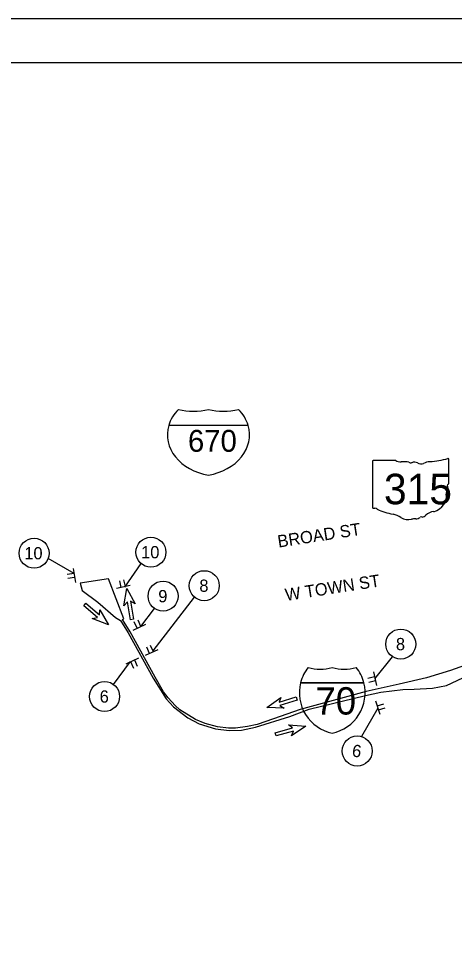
# Model space of a CAD drawing. Extents: x 0 to 680, y 0 to 440.
# Drawn here: x 318.1 to 417.5, y 225.4 to 440 of the extents above; entities that cross this region are included whole.
import ezdxf

# ---------------------------------------------------------------- set-up
doc = ezdxf.new("R2010")
doc.units = 0
for name, color, linetype in [('GM_X_Corporation_Text', 7, 'Continuous'), ('GM_X_County', 7, 'Continuous'), ('GM_X_Major_Lake', 7, 'Continuous'), ('GM_X_Major_River', 7, 'Continuous'), ('GM_X_Major_River_Text', 7, 'Continuous'), ('GM_X_Minor_Lake', 7, 'Continuous'), ('GM_X_Minor_River_Text', 7, 'Continuous'), ('GM_X_Unincorporated_Location', 7, 'Continuous'), ('GM_X_Unincorporated_Text', 7, 'Continuous')]:
    doc.layers.add(name, color=color, linetype=linetype)

msp = doc.modelspace()

# ---------------------------------------------------------------- linework, layer by layer
at = {"layer": 'GM_X_Corporation_Text'}
msp.add_lwpolyline([(419.85, 292.29), (416.65, 291.16), (411.19, 289.5), (404.98, 288.04), (397.46, 286.34), (382.37, 282.22), (376.24, 280.1), (372.51, 278.83), (370.32, 278.34), (367.58, 277.98), (365.97, 277.99), (363.45, 278.29), (360.65, 279.07), (358.44, 279.98), (354.91, 282.18), (353.81, 283.15), (352.17, 284.92), (351.18, 286.31), (349.21, 289.64), (343.56, 300.01), (341.8, 302.82), (342.05, 302.96), (338.55, 312.08), (332.09, 311.12), (332.58, 309.43), (336.11, 306.79), (340.18, 303.22), (341.35, 302.58), (343.11, 299.77), (348.76, 289.39), (351.72, 284.68), (353.39, 282.88), (356.68, 280.34), (359.3, 278.98), (363.03, 277.82), (366.12, 277.46), (368.92, 277.55), (372.16, 278.18), (379.97, 280.67), (384.44, 282.31), (397.27, 285.46), (400.81, 286.17), (405.8, 286.78), (408.42, 286.86), (412.57, 287.14), (415.79, 287.72), (420.78, 290.12)], dxfattribs=at)
at = {"layer": 'GM_X_County'}
msp.add_lwpolyline([(0, 0), (680, 0), (680, 440), (0, 440)], close=True, dxfattribs=at)
at = {"layer": 'GM_X_Major_Lake'}
for p, q in [((342.1, 305.93), (342.77, 309.84)), ((342.77, 309.84), (342.77, 309.84)), ((342.77, 309.84), (344.67, 306.36)), ((344.67, 306.36), (343.63, 306.95)), ((343.63, 306.95), (344.31, 302.88)), ((332.93, 305.95), (333.42, 306.52)), ((336.07, 303.26), (332.93, 305.95)), ((333.18, 306.23), (333.18, 306.23)), ((333.42, 306.52), (336.55, 303.83)), ((336.55, 303.83), (336.59, 305.03)), ((336.59, 305.03), (338.59, 301.6)), ((342.89, 306.82), (342.1, 305.93)), ((343.57, 302.75), (342.89, 306.82)), ((334.89, 303.05), (336.07, 303.26)), ((338.59, 301.6), (334.89, 303.05)), ((344.31, 302.88), (343.57, 302.75)), ((343.94, 302.82), (343.94, 302.82)), ((338.59, 301.6), (338.59, 301.6)), ((374.76, 282.66), (377.97, 285.01)), ((377.52, 283.9), (381.47, 285.11)), ((377.97, 285.01), (377.52, 283.9)), ((381.69, 284.39), (377.74, 283.18)), ((381.47, 285.11), (381.69, 284.39)), ((381.58, 284.75), (381.58, 284.75)), ((374.76, 282.66), (374.76, 282.66)), ((378.73, 282.51), (374.76, 282.66)), ((377.74, 283.18), (378.73, 282.51)), ((376.65, 276.93), (380.63, 278.02)), ((376.85, 276.21), (376.65, 276.93)), ((380.83, 277.3), (376.85, 276.21)), ((380.63, 278.02), (379.66, 278.72)), ((379.66, 278.72), (383.62, 278.46)), ((383.62, 278.46), (380.35, 276.21)), ((380.35, 276.21), (380.83, 277.3)), ((383.62, 278.46), (383.62, 278.46)), ((376.75, 276.57), (376.75, 276.57))]:
    msp.add_line(p, q, dxfattribs=at)
at = {"layer": 'GM_X_Major_River'}
for p, q in [((370.46, 347.12), (352.33, 347.12)), ((370.46, 347.12), (352.33, 347.12)), ((382.46, 288.35), (396.88, 288.35)), ((396.88, 288.35), (382.46, 288.35)), ((396.88, 288.35), (382.46, 288.35))]:
    msp.add_line(p, q, dxfattribs=at)
for centre, start, end in [((391.55, 286.05), 141.669, 165.8066), ((386.93, 300.83), 253.0091, 286.9909), ((392.41, 300.83), 253.0091, 286.9909), ((387.8, 286.05), 14.1934, 38.331), ((391.55, 286.05), 165.8066, 258.463), ((387.8, 286.05), 281.537, 14.1934)]:
    msp.add_arc(centre, 9.38, start, end, dxfattribs=at)
for centre, start_param, end_param in [((363.74, 344.98), 2.47259, 2.911027), ((357.98, 359.76), 4.415841, 5.008937), ((364.82, 359.76), 4.415841, 5.008937), ((359.06, 344.98), 0.230566, 0.669003), ((363.74, 344.98), 2.911027, 4.511031), ((359.06, 344.98), 4.913747, 6.513751)]:
    msp.add_ellipse(centre, major_axis=(11.72, 0), ratio=0.8, start_param=start_param, end_param=end_param, dxfattribs=at)
at = {"layer": 'GM_X_Minor_Lake'}
for p, q in [((330.71, 313.32), (324.8, 316.72)), ((342.31, 310.2), (346.05, 315.55)), ((348.78, 295.63), (358.24, 307.87)), ((346, 301.18), (349.08, 305.3)), ((399.44, 289.25), (403.45, 294.3)), ((339.76, 287.96), (343.61, 293.17)), ((400.11, 282.54), (396.33, 276.06))]:
    msp.add_line(p, q, dxfattribs=at)
for centre in [(321.59, 317.94), (348.27, 318.17), (360.44, 310.52), (351.04, 308.13), (405.32, 297.18), (337.69, 285.21), (395.37, 272.76)]:
    msp.add_circle(centre, 3.43, dxfattribs=at)
at = {"layer": 'GM_X_Minor_River_Text'}
msp.add_lwpolyline([(30, 430), (670, 430), (670, 10), (30, 10)], close=True, dxfattribs=at)
at = {"layer": 'GM_X_Unincorporated_Location'}
for p, q in [((404.16, 339.13), (399.07, 339.13)), ((416.3, 333.86), (416.3, 339.39)), ((398.9, 338.94), (398.9, 328.38)), ((416.3, 333.86), (416.3, 333.86))]:
    msp.add_line(p, q, dxfattribs=at)
for centre, major_axis, start_param, end_param in [((399.1, 338.97), (0.202, 0), 1.712693, 3.28349), ((405.38, 340.35), (1.96, 0), 4.042523, 4.731795), ((410.1, 353.53), (18.45, 0), 4.814394, 5.042369), ((416.11, 339.41), (0.194, 0), 6.141152, 7.989035), ((406.03, 333.19), (7.02, 0), 1.404758, 1.657858), ((407.62, 339.02), (0.564, 0), 3.836095, 5.185415), ((408.45, 337.8), (1.17, 0), 0.950623, 2.079405), ((409.96, 339.47), (1.41, 0), 4.081561, 5.145723), ((412.45, 335.9), (3.71, 0), 1.699011, 2.107814), ((416.25, 333.45), (0.3, 0), 1.883978, 3.671073), ((414.35, 332.76), (1.8, 0), 5.934695, 6.695948), ((416.09, 333.84), (0.207, 0), 5.05454, 6.418171), ((411.13, 330.84), (4.62, 0), 5.101752, 6.440018), ((416.99, 331.55), (1.31, 0), 2.387724, 3.262537), ((399.1, 328.35), (0.203, 0), 3.00124, 4.508301), ((399.13, 329.44), (1.55, 0), 4.665946, 4.897461), ((399.45, 327.77), (0.56, 0), 0.519207, 1.627899), ((406.51, 337.26), (13.33, 0), 4.195997, 4.488961), ((402.54, 323.63), (4.17, 0), 0.823519, 1.323587), ((410.05, 325.9), (0.397, 0), 1.147584, 2.315152), ((409.88, 327.35), (1.49, 0), 4.937069, 5.64225), ((413.08, 325.41), (2.53, 0), 1.647645, 2.488434), ((407.05, 327.72), (2.65, 0), 4.026481, 4.996735), ((408.58, 324.06), (2.17, 0), 1.495662, 1.94098), ((408.77, 326.92), (1.41, 0), 4.691044, 5.507374)]:
    msp.add_ellipse(centre, major_axis=major_axis, ratio=0.8, start_param=start_param, end_param=end_param, dxfattribs=at)
at = {"layer": 'GM_X_Unincorporated_Text'}
for p, q in [((330.71, 313.32), (329.13, 313.09)), ((330.55, 314.43), (331.01, 311.26)), ((330.85, 312.37), (329.26, 312.14)), ((330.78, 312.85), (330.78, 312.85)), ((341.51, 310.1), (341.15, 311.66)), ((342.44, 310.32), (342.09, 311.88)), ((343.53, 310.56), (340.41, 309.86)), ((341.97, 310.21), (341.97, 310.21)), ((346, 301.18), (345.34, 302.64)), ((347.02, 301.65), (344.11, 300.32)), ((345.13, 300.79), (344.46, 302.24)), ((345.56, 300.98), (345.56, 300.98)), ((347.97, 295.04), (347.33, 296.51)), ((348.85, 295.43), (348.21, 296.89)), ((342.6, 292.7), (345.51, 294.03)), ((349.88, 295.88), (346.94, 294.6)), ((348.41, 295.24), (348.41, 295.24)), ((343.61, 293.17), (344.28, 291.71)), ((344.05, 293.36), (344.05, 293.36)), ((344.49, 293.56), (345.15, 292.11)), ((399.33, 289.72), (397.78, 289.35)), ((399.07, 290.81), (399.82, 287.7)), ((399.56, 288.79), (398, 288.41)), ((399.44, 289.25), (399.44, 289.25)), ((400.6, 281.07), (399.61, 284.11)), ((399.96, 283.05), (401.48, 283.54)), ((400.11, 282.59), (400.11, 282.59)), ((400.26, 282.13), (401.78, 282.63))]:
    msp.add_line(p, q, dxfattribs=at)

# ---------------------------------------------------------------- texts
at = {"layer": 'GM_X_Major_River'}
for s, height, p in [('670', 5, (356.73, 341.1)), ('70', 6.25, (385.83, 281.08))]:
    msp.add_text(s, height=height, dxfattribs=at).set_placement(p)
at = {"layer": 'GM_X_Major_River_Text'}
for s in ['-', '.', ',']:
    msp.add_text(s, height=0.01, dxfattribs=at).set_placement((385.68, 286.24))
msp.add_text('70', height=0.01, rotation=0, dxfattribs=at).set_placement((383.64, 284.17))
at = {"layer": 'GM_X_Minor_Lake'}
for s, rotation, p in [('BROAD ST', 8.7669, (377.41, 319.21)), ('W TOWN ST', 8.7669, (379.14, 307.03)), ('6', 351.9351, (394.06, 271.53))]:
    msp.add_text(s, height=2.8, rotation=rotation, dxfattribs=at).set_placement(p)
for s, p in [('10', (319.36, 316.54)), ('10', (346.04, 316.77)), ('8', (359.33, 309.12)), ('9', (349.95, 306.73)), ('8', (404.22, 295.78)), ('6', (336.57, 283.81))]:
    msp.add_text(s, height=2.8, dxfattribs=at).set_placement(p)
at = {"layer": 'GM_X_Unincorporated_Location'}
msp.add_text('315', height=6.961, dxfattribs=at).set_placement((401.49, 329.12))

doc.saveas('drawing.dxf')
